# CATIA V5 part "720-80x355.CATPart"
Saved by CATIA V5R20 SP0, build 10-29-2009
Part number: 720-80x355
Definition: NONE
Nomenclature: 720-80x355
Source: Unknown
Description: 720-80x355
Bounding box of the stored display mesh (mm): x 0 to 355, y -40 to 40, z -40 to 40
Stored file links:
  C:\Users\Utente\Desktop\IO LAVORO\3D X SITO CF\X SITO\720\720-80x355.CATPart
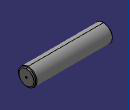
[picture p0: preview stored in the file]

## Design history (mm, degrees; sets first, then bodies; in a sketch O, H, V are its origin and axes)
Body1 "720-80x355" (main body)
  Solid1: solid without history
